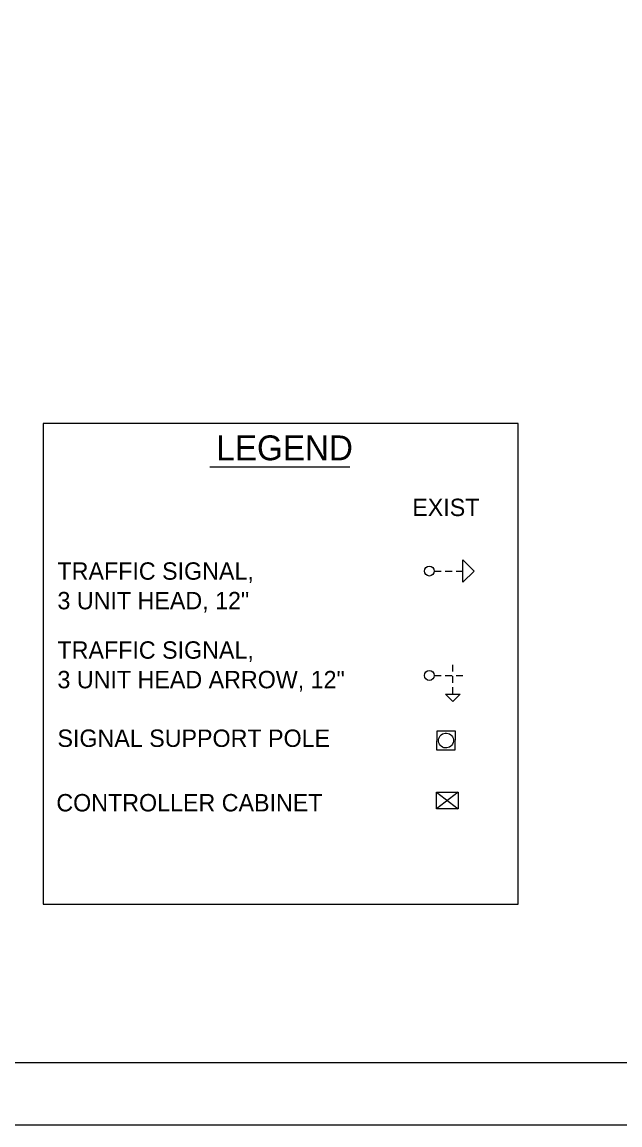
# Model space of a CAD drawing. Extents: x -598712 to 598841, y -1929203 to 1929250.
# Drawn here: x 24.37 to 29.19, y 0 to 8.88 of the extents above; entities that cross this region are included whole.
import ezdxf

# ---------------------------------------------------------------- set-up
doc = ezdxf.new("R2010")
doc.units = 0
for name, color, linetype in [('PM_P_Stop_Line', 7, 'Continuous'), ('SG_P_Controllers', 7, 'Continuous'), ('SG_P_Detection', 7, 'Continuous'), ('SG_P_Heads', 7, 'Continuous'), ('SG_P_Poles', 7, 'Continuous'), ('UT_X_Electric', 7, 'Continuous')]:
    doc.layers.add(name, color=color, linetype=linetype)

msp = doc.modelspace()

# ---------------------------------------------------------------- linework, layer by layer
at = {"layer": 'PM_P_Stop_Line'}
msp.add_lwpolyline([(24.5426, 5.6472), (24.5426, 1.7778), (28.3651, 1.7778), (28.3651, 5.6472), (28.3651, 5.6472)], close=True, dxfattribs=at)
at = {"layer": 'SG_P_Controllers'}
for p, q in [((25.884, 5.298), (27.0096, 5.298)), ((27.6911, 4.4588), (27.7461, 4.4588)), ((27.7786, 4.4588), (27.8336, 4.4588)), ((27.8661, 4.4588), (27.9211, 4.4588)), ((27.7085, 2.6792), (27.8835, 2.5458)), ((27.8835, 2.6792), (27.7085, 2.5458))]:
    msp.add_line(p, q, dxfattribs=at)
for points in [[(27.9211, 4.5488), (28.0111, 4.4588), (27.9211, 4.3688)], [(27.8835, 2.5458), (27.7085, 2.5458), (27.7085, 2.6792), (27.8835, 2.6792)]]:
    msp.add_lwpolyline(points, close=True, dxfattribs=at)
msp.add_circle((27.6511, 4.4588), 0.04, dxfattribs=at)
at = {"layer": 'SG_P_Detection'}
msp.add_lwpolyline([(27.7095, 3.0203), (27.8595, 3.019), (27.8608, 3.169), (27.7108, 3.1703)], close=True, dxfattribs=at)
msp.add_ellipse((27.7851, 3.0946), major_axis=(0.0169, 0.0576), ratio=0.999809, dxfattribs=at)
at = {"layer": 'SG_P_Heads'}
msp.add_lwpolyline([(1.5, 21.5), (33.5, 21.5), (33.5, 0.5), (1.5, 0.5)], close=True, dxfattribs=at)
at = {"layer": 'SG_P_Poles'}
msp.add_lwpolyline([(0, 0), (34, 0), (34, 22), (0, 22)], close=True, dxfattribs=at)
at = {"layer": 'UT_X_Electric'}
for p, q in [((27.8404, 3.6489), (27.8404, 3.7039)), ((27.6911, 3.6181), (27.7461, 3.6181)), ((27.7786, 3.6181), (27.8336, 3.6181)), ((27.8404, 3.5589), (27.8404, 3.6139)), ((27.8661, 3.6181), (27.9211, 3.6181)), ((27.8404, 3.4689), (27.8404, 3.5239))]:
    msp.add_line(p, q, dxfattribs=at)
msp.add_lwpolyline([(27.9004, 3.4689), (27.8404, 3.4089), (27.7804, 3.4689)], close=True, dxfattribs=at)
msp.add_circle((27.6511, 3.6181), 0.04, dxfattribs=at)

# ---------------------------------------------------------------- texts
at = {"layer": 'SG_P_Controllers'}
for s, height, p in [('LEGEND', 0.2, (25.9358, 5.3506)), ('EXIST', 0.14, (27.5134, 4.9012)), ('TRAFFIC SIGNAL, ', 0.14, (24.6566, 4.3888)), ('3 UNIT HEAD, 12"', 0.14, (24.6566, 4.1508)), ('TRAFFIC SIGNAL,', 0.14, (24.6566, 3.753)), ('3 UNIT HEAD ARROW, 12"', 0.14, (24.6566, 3.515)), ('SIGNAL SUPPORT POLE', 0.14, (24.6566, 3.043)), ('CONTROLLER CABINET', 0.14, (24.6476, 2.5238))]:
    msp.add_text(s, height=height, dxfattribs=at).set_placement(p)

doc.saveas('drawing.dxf')
